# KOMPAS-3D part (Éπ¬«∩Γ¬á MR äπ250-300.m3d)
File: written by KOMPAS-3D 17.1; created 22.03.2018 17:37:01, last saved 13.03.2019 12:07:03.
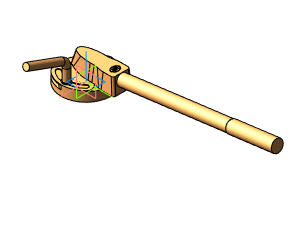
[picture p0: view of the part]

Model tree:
1. Операция без истории:2  (labels: Сталь 20  ГОСТ 1050-2013)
